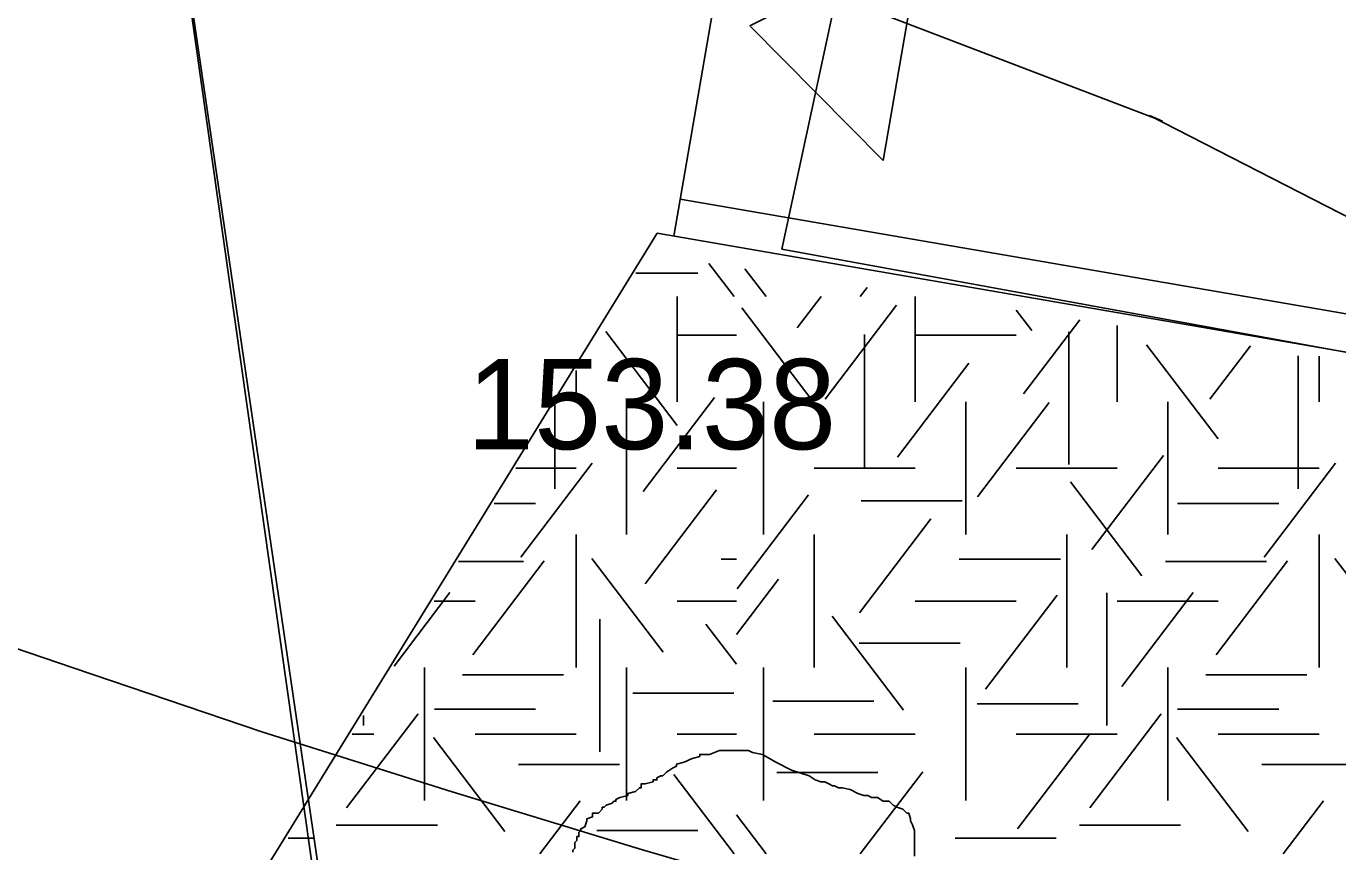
# Model space of a CAD drawing. Extents: x 419101 to 420177, y 4451541 to 4452254.
# Drawn here: x 419929.46 to 419946.9, y 4451859 to 4451869.98 of the extents above; entities that cross this region are included whole.
import ezdxf

# ---------------------------------------------------------------- set-up
doc = ezdxf.new("R2010")
doc.units = 0
for name, color, linetype in [('1_PLAN_ONAMA_SINIRI', 7, 'Continuous'), ('2_KADASTRO', 7, 'Continuous'), ('3_HALİHAZIR', 7, 'Continuous'), ('Level 3', 7, 'Continuous'), ('Level 41', 7, 'Continuous'), ('Level 53', 7, 'Continuous'), ('Level 62', 7, 'Continuous')]:
    doc.layers.add(name, color=color, linetype=linetype)

msp = doc.modelspace()

# ---------------------------------------------------------------- linework, layer by layer
at = {"layer": '1_PLAN_ONAMA_SINIRI'}
for p, q in [((419944.568, 4451868.715), (419933.753, 4451872.855)), ((419954.64, 4451863.529), (419944.392, 4451868.793)), ((419944.392, 4451868.793), (419944.568, 4451868.715))]:
    msp.add_line(p, q, dxfattribs=at)
at = {"layer": '2_KADASTRO'}
msp.add_lwpolyline([(419914.2, 4451877.341), (419930.946, 4451875.186), (419934.685, 4451848.779), (419916.911, 4451847.307), (419916.217, 4451854.99), (419915.914, 4451858.358), (419915.553, 4451862.352), (419915.501, 4451862.931), (419914.917, 4451869.397)], close=True, dxfattribs=at)
at = {"layer": '3_HALİHAZIR'}
msp.add_lwpolyline([(419914.419, 4451875.258), (419914.199, 4451877.32), (419930.913, 4451875.401), (419934.789, 4451848.963), (419916.96, 4451847.443), (419916.774, 4451849.566), (419916.434, 4451849.539), (419916.064, 4451855.399), (419923.107, 4451855.496), (419922.07, 4451864.55), (419921.573, 4451869.575), (419914.653, 4451869.506)], close=True, dxfattribs=at)
at = {"layer": 'Level 3'}
for points in [[(419938.21, 4451860.191), (419938.314, 4451860.243), (419938.417, 4451860.269), (419938.417, 4451860.295), (419938.443, 4451860.295), (419938.469, 4451860.295), (419938.547, 4451860.295), (419938.677, 4451860.347), (419938.781, 4451860.347), (419938.858, 4451860.347), (419938.91, 4451860.347), (419938.988, 4451860.347), (419939.04, 4451860.347), (419939.066, 4451860.347), (419939.118, 4451860.321), (419939.248, 4451860.295), (419939.429, 4451860.191), (419939.637, 4451860.087), (419939.87, 4451860.009), (419939.948, 4451859.957), (419940.026, 4451859.931), (419940.078, 4451859.931), (419940.13, 4451859.905), (419940.181, 4451859.879), (419940.207, 4451859.879), (419940.259, 4451859.853), (419940.311, 4451859.853), (419940.415, 4451859.827), (419940.519, 4451859.775), (419940.596, 4451859.749), (419940.648, 4451859.749), (419940.7, 4451859.723), (419940.752, 4451859.723), (419940.778, 4451859.723), (419940.856, 4451859.672), (419940.934, 4451859.672), (419940.986, 4451859.62), (419941.037, 4451859.594), (419941.115, 4451859.568), (419941.167, 4451859.516), (419941.193, 4451859.516), (419941.219, 4451859.438), (419941.219, 4451859.412), (419941.245, 4451859.36), (419941.271, 4451859.282), (419941.271, 4451859.256), (419941.271, 4451859.178), (419941.271, 4451859.126), (419941.271, 4451859.048), (419941.271, 4451859.022), (419941.271, 4451858.944)], [(419936.731, 4451858.996), (419936.731, 4451859.022), (419936.757, 4451859.048), (419936.757, 4451859.074), (419936.757, 4451859.1), (419936.757, 4451859.126), (419936.783, 4451859.152), (419936.783, 4451859.178), (419936.783, 4451859.204), (419936.809, 4451859.204), (419936.809, 4451859.23), (419936.809, 4451859.256), (419936.835, 4451859.282), (419936.835, 4451859.308), (419936.887, 4451859.334), (419936.913, 4451859.412), (419936.913, 4451859.438), (419936.991, 4451859.464), (419936.991, 4451859.49), (419936.991, 4451859.516), (419937.068, 4451859.516), (419937.12, 4451859.568), (419937.12, 4451859.594), (419937.146, 4451859.594), (419937.172, 4451859.62), (419937.25, 4451859.646), (419937.276, 4451859.672), (419937.302, 4451859.672), (419937.302, 4451859.698), (419937.354, 4451859.723), (419937.458, 4451859.749), (419937.458, 4451859.775), (419937.561, 4451859.801), (419937.613, 4451859.853), (419937.639, 4451859.853), (419937.639, 4451859.879), (419937.639, 4451859.905), (419937.691, 4451859.905), (419937.795, 4451859.931), (419937.795, 4451859.957), (419937.821, 4451859.957), (419937.847, 4451859.957), (419937.847, 4451859.983), (419937.899, 4451860.009), (419937.925, 4451860.009), (419937.976, 4451860.061), (419938.054, 4451860.113), (419938.106, 4451860.139), (419938.106, 4451860.165), (419938.21, 4451860.191)]]:
    msp.add_lwpolyline(points, dxfattribs=at)
at = {"layer": 'Level 41'}
for p, q in [((419938.874, 4451866.383), (419938.538, 4451866.825)), ((419937.568, 4451866.695), (419938.39, 4451866.695)), ((419939.297, 4451866.383), (419939.016, 4451866.752)), ((419940.55, 4451866.383), (419940.643, 4451866.505)), ((419938.115, 4451866.383), (419938.115, 4451864.985)), ((419938.115, 4451866.383), (419938.115, 4451864.985)), ((419939.713, 4451865.966), (419940.03, 4451866.383)), ((419940.084, 4451865.02), (419941.033, 4451866.27)), ((419941.279, 4451866.383), (419941.279, 4451864.985)), ((419939.924, 4451864.985), (419938.975, 4451866.235)), ((419942.828, 4451865.931), (419942.62, 4451866.204)), ((419938.116, 4451864.669), (419937.167, 4451865.918)), ((419942.721, 4451865.089), (419943.47, 4451866.075)), ((419943.321, 4451865.916), (419943.321, 4451864.149)), ((419943.965, 4451866), (419943.965, 4451864.985)), ((419938.115, 4451865.869), (419938.903, 4451865.869)), ((419940.604, 4451865.881), (419940.604, 4451864.114)), ((419941.279, 4451865.869), (419942.622, 4451865.869)), ((419945.305, 4451864.494), (419944.356, 4451865.743)), ((419945.198, 4451865.02), (419945.737, 4451865.73)), ((419946.369, 4451865.595), (419946.369, 4451863.828)), ((419946.651, 4451865.591), (419946.651, 4451864.985)), ((419936.772, 4451865.402), (419936.772, 4451864.985)), ((419941.044, 4451864.248), (419941.993, 4451865.498)), ((419937.664, 4451863.792), (419938.613, 4451865.042)), ((419936.49, 4451864.944), (419936.49, 4451863.828)), ((419937.444, 4451864.985), (419937.444, 4451863.218)), ((419937.444, 4451864.985), (419937.444, 4451863.218)), ((419939.265, 4451863.218), (419939.265, 4451864.985)), ((419941.951, 4451864.985), (419941.951, 4451863.218)), ((419942.11, 4451863.723), (419943.059, 4451864.973)), ((419944.637, 4451864.985), (419944.637, 4451863.218)), ((419936.039, 4451862.917), (419936.988, 4451864.167)), ((419943.627, 4451863.022), (419944.578, 4451864.271)), ((419945.918, 4451862.917), (419946.867, 4451864.167)), ((419935.971, 4451864.101), (419936.772, 4451864.101)), ((419938.115, 4451864.101), (419938.903, 4451864.101)), ((419939.936, 4451864.101), (419941.279, 4451864.101)), ((419942.622, 4451864.101), (419943.965, 4451864.101)), ((419945.308, 4451864.101), (419946.651, 4451864.101)), ((419944.293, 4451862.672), (419943.343, 4451863.921)), ((419937.69, 4451862.566), (419938.64, 4451863.815)), ((419938.913, 4451862.497), (419939.862, 4451863.746)), ((419940.56, 4451863.667), (419941.903, 4451863.667)), ((419935.682, 4451863.631), (419936.232, 4451863.631)), ((419944.768, 4451863.631), (419946.111, 4451863.631)), ((419940.538, 4451862.18), (419941.487, 4451863.43)), ((419936.772, 4451863.218), (419936.772, 4451861.451)), ((419939.936, 4451863.218), (419939.936, 4451861.451)), ((419943.294, 4451863.218), (419943.294, 4451861.451)), ((419946.651, 4451863.218), (419946.651, 4451861.451)), ((419935.208, 4451862.861), (419936.072, 4451862.861)), ((419935.399, 4451861.62), (419936.349, 4451862.87)), ((419937.929, 4451861.654), (419936.98, 4451862.903)), ((419938.699, 4451862.894), (419938.903, 4451862.894)), ((419941.866, 4451862.894), (419943.209, 4451862.894)), ((419944.608, 4451862.861), (419945.951, 4451862.861)), ((419945.278, 4451861.62), (419946.228, 4451862.87)), ((419947.808, 4451861.654), (419946.859, 4451862.903)), ((419938.903, 4451861.888), (419939.462, 4451862.624)), ((419934.353, 4451861.471), (419935.096, 4451862.449)), ((419943.826, 4451862.446), (419943.826, 4451860.678)), ((419944.026, 4451861.2), (419944.975, 4451862.449)), ((419934.884, 4451862.334), (419935.429, 4451862.334)), ((419938.115, 4451862.334), (419938.903, 4451862.334)), ((419941.279, 4451862.334), (419942.622, 4451862.334)), ((419942.215, 4451861.164), (419943.165, 4451862.414)), ((419943.965, 4451862.334), (419945.308, 4451862.334)), ((419937.09, 4451862.096), (419937.09, 4451860.328)), ((419941.123, 4451860.883), (419940.174, 4451862.133)), ((419938.903, 4451861.494), (419938.497, 4451862.028)), ((419940.533, 4451861.774), (419941.876, 4451861.774)), ((419934.758, 4451859.683), (419934.758, 4451861.451)), ((419937.444, 4451859.683), (419937.444, 4451861.451)), ((419939.265, 4451859.683), (419939.265, 4451861.451)), ((419941.951, 4451859.683), (419941.951, 4451861.451)), ((419944.637, 4451859.683), (419944.637, 4451861.451)), ((419935.263, 4451861.353), (419936.606, 4451861.353)), ((419945.142, 4451861.353), (419946.485, 4451861.353)), ((419937.526, 4451861.108), (419938.869, 4451861.108)), ((419934.889, 4451860.897), (419936.232, 4451860.897)), ((419939.388, 4451861.002), (419940.731, 4451861.002)), ((419942.105, 4451860.968), (419943.448, 4451860.968)), ((419944.768, 4451860.897), (419946.111, 4451860.897)), ((419933.722, 4451859.586), (419934.671, 4451860.836)), ((419933.947, 4451860.812), (419933.947, 4451860.678)), ((419943.601, 4451859.586), (419944.55, 4451860.836)), ((419933.797, 4451860.567), (419934.086, 4451860.567)), ((419935.825, 4451859.272), (419934.875, 4451860.521)), ((419935.429, 4451860.567), (419936.772, 4451860.567)), ((419938.115, 4451860.567), (419938.903, 4451860.567)), ((419939.936, 4451860.567), (419941.279, 4451860.567)), ((419942.622, 4451860.567), (419943.965, 4451860.567)), ((419942.641, 4451859.307), (419943.59, 4451860.556)), ((419945.704, 4451859.272), (419944.754, 4451860.521)), ((419945.308, 4451860.567), (419946.651, 4451860.567)), ((419936.008, 4451860.16), (419937.351, 4451860.16)), ((419945.887, 4451860.16), (419947.23, 4451860.16)), ((419938.874, 4451858.974), (419938.072, 4451860.03)), ((419939.442, 4451860.056), (419940.784, 4451860.056)), ((419940.55, 4451858.974), (419941.379, 4451860.065)), ((419936.291, 4451858.974), (419936.828, 4451859.68)), ((419946.17, 4451858.974), (419946.707, 4451859.68)), ((419939.297, 4451858.974), (419938.903, 4451859.492)), ((419933.585, 4451859.355), (419934.928, 4451859.355)), ((419937.047, 4451859.286), (419938.39, 4451859.286)), ((419943.464, 4451859.355), (419944.807, 4451859.355)), ((419932.943, 4451859.18), (419933.276, 4451859.18)), ((419941.812, 4451859.18), (419943.155, 4451859.18))]:
    msp.add_line(p, q, dxfattribs=at)
at = {"layer": 'Level 53'}
for p, q in [((419929.296, 4451861.718), (419930.086, 4451861.448)), ((419930.086, 4451861.448), (419932.596, 4451860.598)), ((419932.596, 4451860.598), (419935.126, 4451859.798)), ((419935.126, 4451859.798), (419937.656, 4451859.028)), ((419937.656, 4451859.028), (419940.206, 4451858.288))]:
    msp.add_line(p, q, dxfattribs=at)
at = {"layer": 'Level 62'}
for p, q in [((419939.089, 4451873.1), (419938.07, 4451867.187)), ((419939.089, 4451873.1), (419938.07, 4451867.187)), ((419939.089, 4451873.1), (419938.07, 4451867.187)), ((419940.765, 4451872.885), (419939.509, 4451867.014)), ((419940.765, 4451872.885), (419939.509, 4451867.014)), ((419940.765, 4451872.885), (419939.509, 4451867.014)), ((419938.154, 4451867.679), (419950.831, 4451865.494)), ((419938.154, 4451867.679), (419950.831, 4451865.494)), ((419938.154, 4451867.679), (419950.831, 4451865.494)), ((419928.371, 4451851.84), (419937.85, 4451867.225)), ((419937.85, 4451867.225), (419951.239, 4451864.917)), ((419939.509, 4451867.014), (419961.513, 4451862.988)), ((419939.509, 4451867.014), (419961.513, 4451862.988)), ((419939.509, 4451867.014), (419961.513, 4451862.988))]:
    msp.add_line(p, q, dxfattribs=at)
msp.add_lwpolyline([(419940.854, 4451868.194), (419939.083, 4451869.983), (419941.358, 4451871.119)], close=True, dxfattribs=at)
msp.add_lwpolyline([(419940.854, 4451868.194), (419939.083, 4451869.983), (419941.358, 4451871.119)], close=True, dxfattribs=at)
msp.add_lwpolyline([(419940.854, 4451868.194), (419939.083, 4451869.983), (419941.358, 4451871.119)], close=True, dxfattribs=at)

# ---------------------------------------------------------------- texts
at = {"layer": '3_HALİHAZIR'}
msp.add_text('153.38 ', height=1.2, rotation=359.9971, dxfattribs=at).set_placement((419935.321, 4451864.354))

doc.saveas('drawing.dxf')
